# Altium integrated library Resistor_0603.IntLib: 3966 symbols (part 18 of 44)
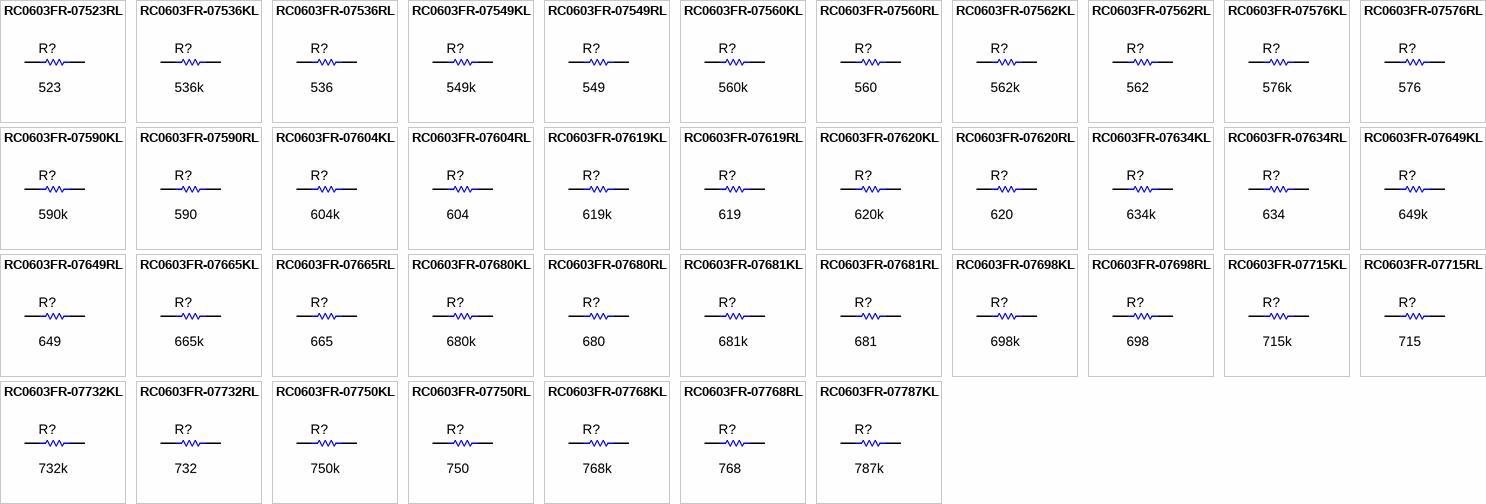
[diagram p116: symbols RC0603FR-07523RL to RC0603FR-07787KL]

## RC0603FR-07576RL
designator R?  ValueDisplayed: 576  (hidden comment: RC0603FR-07576RL)
RES, 576, 1%, 0.1 W, 0603; Manufacturer: Yageo America; CompType: Resistor; Value: 576; Value_Code: 576R; Tolerance_%: 1; Power_W: 0.1; Value2: 0.1W; VDC_V: 150; TempCo: 200 ppm/C; SizeArea_mm2: 1.28; SizeX_mm: 1.6; SizeY_mm: 0.8; EIA_Code: E96; U/M: EA; AEC Category: Q200; Green_Lifecycle: Active; Green_REACh: Passed
signal-integrity model Resistor
simulation model Resistor
footprint 0603
footprint 0603M
footprint 0603L
footprint 0603_HV
footprint 0603S
pins: 1, 2

## RC0603FR-07590KL
designator R?  ValueDisplayed: 590k  (hidden comment: RC0603FR-07590KL)
RES, 590 k, 1%, 0.1 W, 0603; Manufacturer: Yageo America; CompType: Resistor; Value: 590k; Res_ohm: 590000; Tolerance_%: 1; Power_W: 0.1; Value2: 0.1W; VDC_V: 150; TempCo: 200 ppm/C; SizeArea_mm2: 1.28; SizeX_mm: 1.6; SizeY_mm: 0.8; EIA_Code: E96; U/M: EA; AEC Category: Q200
signal-integrity model Resistor
simulation model Resistor
footprint 0603
footprint 0603M
footprint 0603L
footprint 0603_HV
footprint 0603S
pins: 1, 2

## RC0603FR-07590RL
designator R?  ValueDisplayed: 590  (hidden comment: RC0603FR-07590RL)
RES, 590, 1%, 0.1 W, 0603; Manufacturer: Yageo America; CompType: Resistor; Value: 590; Value_Code: 590R; Tolerance_%: 1; Power_W: 0.1; Value2: 0.1W; VDC_V: 150; TempCo: 200 ppm/C; SizeArea_mm2: 1.28; SizeX_mm: 1.6; SizeY_mm: 0.8; EIA_Code: E96; U/M: EA; AEC Category: Q200
signal-integrity model Resistor
simulation model Resistor
footprint 0603
footprint 0603M
footprint 0603L
footprint 0603_HV
footprint 0603S
pins: 1, 2

## RC0603FR-07604KL
designator R?  ValueDisplayed: 604k  (hidden comment: RC0603FR-07604KL)
RES, 604 k, 1%, 0.1 W, 0603; Manufacturer: Yageo America; CompType: Resistor; Value: 604k; Res_ohm: 604000; Tolerance_%: 1; Power_W: 0.1; Value2: 0.1W; VDC_V: 150; TempCo: 200 ppm/C; SizeArea_mm2: 1.28; SizeX_mm: 1.6; SizeY_mm: 0.8; EIA_Code: E96; U/M: EA; AEC Category: Q200; Green_Lifecycle: Active; Green_REACh: Passed
signal-integrity model Resistor
simulation model Resistor
footprint 0603
footprint 0603M
footprint 0603L
footprint 0603_HV
footprint 0603S
pins: 1, 2

## RC0603FR-07604RL
designator R?  ValueDisplayed: 604  (hidden comment: RC0603FR-07604RL)
RES, 604, 1%, 0.1 W, 0603; Manufacturer: Yageo America; CompType: Resistor; Value: 604; Value_Code: 604R; Tolerance_%: 1; Power_W: 0.1; Value2: 0.1W; VDC_V: 150; TempCo: 200 ppm/C; SizeArea_mm2: 1.28; SizeX_mm: 1.6; SizeY_mm: 0.8; EIA_Code: E96; U/M: EA; AEC Category: Q200; Green_Lifecycle: Active; Green_REACh: Passed
signal-integrity model Resistor
simulation model Resistor
footprint 0603
footprint 0603M
footprint 0603L
footprint 0603_HV
footprint 0603S
pins: 1, 2

## RC0603FR-07619KL
designator R?  ValueDisplayed: 619k  (hidden comment: RC0603FR-07619KL)
RES, 619 k, 1%, 0.1 W, 0603; Manufacturer: Yageo America; CompType: Resistor; Value: 619k; Res_ohm: 619000; Tolerance_%: 1; Power_W: 0.1; Value2: 0.1W; VDC_V: 150; TempCo: 200 ppm/C; SizeArea_mm2: 1.28; SizeX_mm: 1.6; SizeY_mm: 0.8; EIA_Code: E96; U/M: EA; AEC Category: Q200; Green_Lifecycle: Active; Green_REACh: Passed
signal-integrity model Resistor
simulation model Resistor
footprint 0603
footprint 0603M
footprint 0603L
footprint 0603_HV
footprint 0603S
pins: 1, 2

## RC0603FR-07619RL
designator R?  ValueDisplayed: 619  (hidden comment: RC0603FR-07619RL)
RES, 619, 1%, 0.1 W, 0603; Manufacturer: Yageo America; CompType: Resistor; Value: 619; Value_Code: 619R; Tolerance_%: 1; Power_W: 0.1; Value2: 0.1W; VDC_V: 150; TempCo: 200 ppm/C; SizeArea_mm2: 1.28; SizeX_mm: 1.6; SizeY_mm: 0.8; EIA_Code: E96; U/M: EA; AEC Category: Q200; Green_Lifecycle: Active; Green_REACh: Passed
signal-integrity model Resistor
simulation model Resistor
footprint 0603
footprint 0603M
footprint 0603L
footprint 0603_HV
footprint 0603S
pins: 1, 2

## RC0603FR-07620KL
designator R?  ValueDisplayed: 620k  (hidden comment: RC0603FR-07620KL)
RES, 620 k, 1%, 0.1 W, 0603; Manufacturer: Yageo America; CompType: Resistor; Value: 620k; Res_ohm: 620000; Tolerance_%: 1; Power_W: 0.1; Value2: 0.1W; VDC_V: 150; TempCo: 200 ppm/C; SizeArea_mm2: 1.28; SizeX_mm: 1.6; SizeY_mm: 0.8; U/M: EA; AEC Category: Q200; Green_Lifecycle: Active; Green_REACh: Passed
signal-integrity model Resistor
simulation model Resistor
footprint 0603
footprint 0603M
footprint 0603L
footprint 0603_HV
footprint 0603S
pins: 1, 2

## RC0603FR-07620RL
designator R?  ValueDisplayed: 620  (hidden comment: RC0603FR-07620RL)
RES, 620, 1%, 0.1 W, 0603; Manufacturer: Yageo America; CompType: Resistor; Value: 620; Value_Code: 620R; Tolerance_%: 1; Power_W: 0.1; Value2: 0.1W; VDC_V: 150; TempCo: 200 ppm/C; SizeArea_mm2: 1.28; SizeX_mm: 1.6; SizeY_mm: 0.8; U/M: EA; AEC Category: Q200
signal-integrity model Resistor
simulation model Resistor
footprint 0603
footprint 0603M
footprint 0603L
footprint 0603_HV
footprint 0603S
pins: 1, 2

## RC0603FR-07634KL
designator R?  ValueDisplayed: 634k  (hidden comment: RC0603FR-07634KL)
RES, 634 k, 1%, 0.1 W, 0603; Manufacturer: Yageo America; CompType: Resistor; Value: 634k; Res_ohm: 634000; Tolerance_%: 1; Power_W: 0.1; Value2: 0.1W; VDC_V: 150; TempCo: 200 ppm/C; SizeArea_mm2: 1.28; SizeX_mm: 1.6; SizeY_mm: 0.8; EIA_Code: E96; U/M: EA; AEC Category: Q200
signal-integrity model Resistor
simulation model Resistor
footprint 0603
footprint 0603M
footprint 0603L
footprint 0603_HV
footprint 0603S
pins: 1, 2

## RC0603FR-07634RL
designator R?  ValueDisplayed: 634  (hidden comment: RC0603FR-07634RL)
RES, 634, 1%, 0.1 W, 0603; Manufacturer: Yageo America; CompType: Resistor; Value: 634; Value_Code: 634R; Tolerance_%: 1; Power_W: 0.1; Value2: 0.1W; VDC_V: 150; TempCo: 200 ppm/C; SizeArea_mm2: 1.28; SizeX_mm: 1.6; SizeY_mm: 0.8; EIA_Code: E96; U/M: EA; AEC Category: Q200
signal-integrity model Resistor
simulation model Resistor
footprint 0603
footprint 0603M
footprint 0603L
footprint 0603_HV
footprint 0603S
pins: 1, 2

## RC0603FR-07649KL
designator R?  ValueDisplayed: 649k  (hidden comment: RC0603FR-07649KL)
RES, 649 k, 1%, 0.1 W, 0603; Manufacturer: Yageo America; CompType: Resistor; Value: 649k; Res_ohm: 649000; Tolerance_%: 1; Power_W: 0.1; Value2: 0.1W; VDC_V: 150; TempCo: 200 ppm/C; SizeArea_mm2: 1.28; SizeX_mm: 1.6; SizeY_mm: 0.8; EIA_Code: E96; U/M: EA; AEC Category: Q200
signal-integrity model Resistor
simulation model Resistor
footprint 0603
footprint 0603M
footprint 0603L
footprint 0603_HV
footprint 0603S
pins: 1, 2

## RC0603FR-07649RL
designator R?  ValueDisplayed: 649  (hidden comment: RC0603FR-07649RL)
RES, 649, 1%, 0.1 W, 0603; Manufacturer: Yageo America; CompType: Resistor; Value: 649; Value_Code: 649R; Tolerance_%: 1; Power_W: 0.1; Value2: 0.1W; VDC_V: 150; TempCo: 200 ppm/C; SizeArea_mm2: 1.28; SizeX_mm: 1.6; SizeY_mm: 0.8; EIA_Code: E96; U/M: EA; AEC Category: Q200; Green_Lifecycle: Active; Green_REACh: Passed
signal-integrity model Resistor
simulation model Resistor
footprint 0603
footprint 0603M
footprint 0603L
footprint 0603_HV
footprint 0603S
pins: 1, 2

## RC0603FR-07665KL
designator R?  ValueDisplayed: 665k  (hidden comment: RC0603FR-07665KL)
RES, 665 k, 1%, 0.1 W, 0603; Manufacturer: Yageo America; CompType: Resistor; Value: 665k; Res_ohm: 665000; Tolerance_%: 1; Power_W: 0.1; Value2: 0.1W; VDC_V: 150; TempCo: 200 ppm/C; SizeArea_mm2: 1.28; SizeX_mm: 1.6; SizeY_mm: 0.8; EIA_Code: E96; U/M: EA; AEC Category: Q200
signal-integrity model Resistor
simulation model Resistor
footprint 0603
footprint 0603M
footprint 0603L
footprint 0603_HV
footprint 0603S
pins: 1, 2

## RC0603FR-07665RL
designator R?  ValueDisplayed: 665  (hidden comment: RC0603FR-07665RL)
RES, 665, 1%, 0.1 W, 0603; Manufacturer: Yageo America; CompType: Resistor; Value: 665; Value_Code: 665R; Tolerance_%: 1; Power_W: 0.1; Value2: 0.1W; VDC_V: 150; TempCo: 200 ppm/C; SizeArea_mm2: 1.28; SizeX_mm: 1.6; SizeY_mm: 0.8; EIA_Code: E96; U/M: EA; AEC Category: Q200
signal-integrity model Resistor
simulation model Resistor
footprint 0603
footprint 0603M
footprint 0603L
footprint 0603_HV
footprint 0603S
pins: 1, 2

## RC0603FR-07680KL
designator R?  ValueDisplayed: 680k  (hidden comment: RC0603FR-07680KL)
RES, 680 k, 1%, 0.1 W, 0603; Manufacturer: Yageo America; CompType: Resistor; Value: 680k; Res_ohm: 680000; Tolerance_%: 1; Power_W: 0.1; Value2: 0.1W; VDC_V: 150; TempCo: 200 ppm/C; SizeArea_mm2: 1.28; SizeX_mm: 1.6; SizeY_mm: 0.8; U/M: EA; AEC Category: Q200; Green_Lifecycle: Active; Green_REACh: Passed
signal-integrity model Resistor
simulation model Resistor
footprint 0603
footprint 0603M
footprint 0603L
footprint 0603_HV
footprint 0603S
pins: 1, 2

## RC0603FR-07680RL
designator R?  ValueDisplayed: 680  (hidden comment: RC0603FR-07680RL)
RES, 680, 1%, 0.1 W, 0603; Manufacturer: Yageo America; CompType: Resistor; Value: 680; Value_Code: 680R; Tolerance_%: 1; Power_W: 0.1; Value2: 0.1W; VDC_V: 150; TempCo: 200 ppm/C; SizeArea_mm2: 1.28; SizeX_mm: 1.6; SizeY_mm: 0.8; U/M: EA; AEC Category: Q200; Green_Lifecycle: Active; Green_REACh: Passed
signal-integrity model Resistor
simulation model Resistor
footprint 0603
footprint 0603M
footprint 0603L
footprint 0603_HV
footprint 0603S
pins: 1, 2

## RC0603FR-07681KL
designator R?  ValueDisplayed: 681k  (hidden comment: RC0603FR-07681KL)
RES, 681 k, 1%, 0.1 W, 0603; Manufacturer: Yageo America; CompType: Resistor; Value: 681k; Res_ohm: 681000; Tolerance_%: 1; Power_W: 0.1; Value2: 0.1W; VDC_V: 150; TempCo: 200 ppm/C; SizeArea_mm2: 1.28; SizeX_mm: 1.6; SizeY_mm: 0.8; EIA_Code: E96; U/M: EA; AEC Category: Q200
signal-integrity model Resistor
simulation model Resistor
footprint 0603
footprint 0603M
footprint 0603L
footprint 0603_HV
footprint 0603S
pins: 1, 2

## RC0603FR-07681RL
designator R?  ValueDisplayed: 681  (hidden comment: RC0603FR-07681RL)
RES, 681, 1%, 0.1 W, 0603; Manufacturer: Yageo America; CompType: Resistor; Value: 681; Value_Code: 681R; Tolerance_%: 1; Power_W: 0.1; Value2: 0.1W; VDC_V: 150; TempCo: 200 ppm/C; SizeArea_mm2: 1.28; SizeX_mm: 1.6; SizeY_mm: 0.8; EIA_Code: E96; U/M: EA; AEC Category: Q200
signal-integrity model Resistor
simulation model Resistor
footprint 0603
footprint 0603M
footprint 0603L
footprint 0603_HV
footprint 0603S
pins: 1, 2

## RC0603FR-07698KL
designator R?  ValueDisplayed: 698k  (hidden comment: RC0603FR-07698KL)
RES, 698 k, 1%, 0.1 W, 0603; Manufacturer: Yageo America; CompType: Resistor; Value: 698k; Res_ohm: 698000; Tolerance_%: 1; Power_W: 0.1; Value2: 0.1W; VDC_V: 150; TempCo: 200 ppm/C; SizeArea_mm2: 1.28; SizeX_mm: 1.6; SizeY_mm: 0.8; EIA_Code: E96; U/M: EA; AEC Category: Q200
signal-integrity model Resistor
simulation model Resistor
footprint 0603
footprint 0603M
footprint 0603L
footprint 0603_HV
footprint 0603S
pins: 1, 2

## RC0603FR-07698RL
designator R?  ValueDisplayed: 698  (hidden comment: RC0603FR-07698RL)
RES, 698, 1%, 0.1 W, 0603; Manufacturer: Yageo America; CompType: Resistor; Value: 698; Value_Code: 698R; Tolerance_%: 1; Power_W: 0.1; Value2: 0.1W; VDC_V: 150; TempCo: 200 ppm/C; SizeArea_mm2: 1.28; SizeX_mm: 1.6; SizeY_mm: 0.8; EIA_Code: E96; U/M: EA; AEC Category: Q200
signal-integrity model Resistor
simulation model Resistor
footprint 0603
footprint 0603M
footprint 0603L
footprint 0603_HV
footprint 0603S
pins: 1, 2

## RC0603FR-07715KL
designator R?  ValueDisplayed: 715k  (hidden comment: RC0603FR-07715KL)
RES, 715 k, 1%, 0.1 W, 0603; Manufacturer: Yageo America; CompType: Resistor; Value: 715k; Res_ohm: 715000; Tolerance_%: 1; Power_W: 0.1; Value2: 0.1W; VDC_V: 150; TempCo: 200 ppm/C; SizeArea_mm2: 1.28; SizeX_mm: 1.6; SizeY_mm: 0.8; EIA_Code: E96; U/M: EA; AEC Category: Q200
signal-integrity model Resistor
simulation model Resistor
footprint 0603
footprint 0603M
footprint 0603L
footprint 0603_HV
footprint 0603S
pins: 1, 2

## RC0603FR-07715RL
designator R?  ValueDisplayed: 715  (hidden comment: RC0603FR-07715RL)
RES, 715, 1%, 0.1 W, 0603; Manufacturer: Yageo America; CompType: Resistor; Value: 715; Value_Code: 715R; Tolerance_%: 1; Power_W: 0.1; Value2: 0.1W; VDC_V: 150; TempCo: 200 ppm/C; SizeArea_mm2: 1.28; SizeX_mm: 1.6; SizeY_mm: 0.8; EIA_Code: E96; U/M: EA; AEC Category: Q200; Green_Lifecycle: Active; Green_REACh: Passed
signal-integrity model Resistor
simulation model Resistor
footprint 0603
footprint 0603M
footprint 0603L
footprint 0603_HV
footprint 0603S
pins: 1, 2

## RC0603FR-07732KL
designator R?  ValueDisplayed: 732k  (hidden comment: RC0603FR-07732KL)
RES, 732 k, 1%, 0.1 W, 0603; Manufacturer: Yageo America; CompType: Resistor; Value: 732k; Res_ohm: 732000; Tolerance_%: 1; Power_W: 0.1; Value2: 0.1W; VDC_V: 150; TempCo: 200 ppm/C; SizeArea_mm2: 1.28; SizeX_mm: 1.6; SizeY_mm: 0.8; EIA_Code: E96; U/M: EA; AEC Category: Q200
signal-integrity model Resistor
simulation model Resistor
footprint 0603
footprint 0603M
footprint 0603L
footprint 0603_HV
footprint 0603S
pins: 1, 2

## RC0603FR-07732RL
designator R?  ValueDisplayed: 732  (hidden comment: RC0603FR-07732RL)
RES, 732, 1%, 0.1 W, 0603; Manufacturer: Yageo America; CompType: Resistor; Value: 732; Value_Code: 732R; Tolerance_%: 1; Power_W: 0.1; Value2: 0.1W; VDC_V: 150; TempCo: 200 ppm/C; SizeArea_mm2: 1.28; SizeX_mm: 1.6; SizeY_mm: 0.8; EIA_Code: E96; U/M: EA; AEC Category: Q200; Green_Lifecycle: Active; Green_REACh: Passed
signal-integrity model Resistor
simulation model Resistor
footprint 0603
footprint 0603M
footprint 0603L
footprint 0603_HV
footprint 0603S
pins: 1, 2

## RC0603FR-07750KL
designator R?  ValueDisplayed: 750k  (hidden comment: RC0603FR-07750KL)
RES, 750 k, 1%, 0.1 W, 0603; Manufacturer: Yageo America; CompType: Resistor; Value: 750k; Res_ohm: 750000; Tolerance_%: 1; Power_W: 0.1; Value2: 0.1W; VDC_V: 150; TempCo: 200 ppm/C; SizeArea_mm2: 1.28; SizeX_mm: 1.6; SizeY_mm: 0.8; EIA_Code: E96; U/M: EA; AEC Category: Q200
signal-integrity model Resistor
simulation model Resistor
footprint 0603
footprint 0603M
footprint 0603L
footprint 0603_HV
footprint 0603S
pins: 1, 2

## RC0603FR-07750RL
designator R?  ValueDisplayed: 750  (hidden comment: RC0603FR-07750RL)
RES, 750, 1%, 0.1 W, 0603; Manufacturer: Yageo America; CompType: Resistor; Value: 750; Value_Code: 750R; Tolerance_%: 1; Power_W: 0.1; Value2: 0.1W; VDC_V: 150; TempCo: 200 ppm/C; SizeArea_mm2: 1.28; SizeX_mm: 1.6; SizeY_mm: 0.8; EIA_Code: E96; U/M: EA; AEC Category: Q200; Green_Lifecycle: Active; Green_REACh: Passed
signal-integrity model Resistor
simulation model Resistor
footprint 0603
footprint 0603M
footprint 0603L
footprint 0603_HV
footprint 0603S
pins: 1, 2

## RC0603FR-07768KL
designator R?  ValueDisplayed: 768k  (hidden comment: RC0603FR-07768KL)
RES, 768 k, 1%, 0.1 W, 0603; Manufacturer: Yageo America; CompType: Resistor; Value: 768k; Res_ohm: 768000; Tolerance_%: 1; Power_W: 0.1; Value2: 0.1W; VDC_V: 150; TempCo: 200 ppm/C; SizeArea_mm2: 1.28; SizeX_mm: 1.6; SizeY_mm: 0.8; EIA_Code: E96; U/M: EA; AEC Category: Q200; Green_Lifecycle: Active; Green_REACh: Passed
signal-integrity model Resistor
simulation model Resistor
footprint 0603
footprint 0603M
footprint 0603L
footprint 0603_HV
footprint 0603S
pins: 1, 2

## RC0603FR-07768RL
designator R?  ValueDisplayed: 768  (hidden comment: RC0603FR-07768RL)
RES, 768, 1%, 0.1 W, 0603; Manufacturer: Yageo America; CompType: Resistor; Value: 768; Value_Code: 768R; Tolerance_%: 1; Power_W: 0.1; Value2: 0.1W; VDC_V: 150; TempCo: 200 ppm/C; SizeArea_mm2: 1.28; SizeX_mm: 1.6; SizeY_mm: 0.8; EIA_Code: E96; U/M: EA; AEC Category: Q200; Green_Lifecycle: Active; Green_REACh: Passed
signal-integrity model Resistor
simulation model Resistor
footprint 0603
footprint 0603M
footprint 0603L
footprint 0603_HV
footprint 0603S
pins: 1, 2

## RC0603FR-07787KL
designator R?  ValueDisplayed: 787k  (hidden comment: RC0603FR-07787KL)
RES, 787 k, 1%, 0.1 W, 0603; Manufacturer: Yageo America; CompType: Resistor; Value: 787k; Res_ohm: 787000; Tolerance_%: 1; Power_W: 0.1; Value2: 0.1W; VDC_V: 150; TempCo: 200 ppm/C; SizeArea_mm2: 1.28; SizeX_mm: 1.6; SizeY_mm: 0.8; EIA_Code: E96; U/M: EA; AEC Category: Q200
signal-integrity model Resistor
simulation model Resistor
footprint 0603
footprint 0603M
footprint 0603L
footprint 0603_HV
footprint 0603S
pins: 1, 2

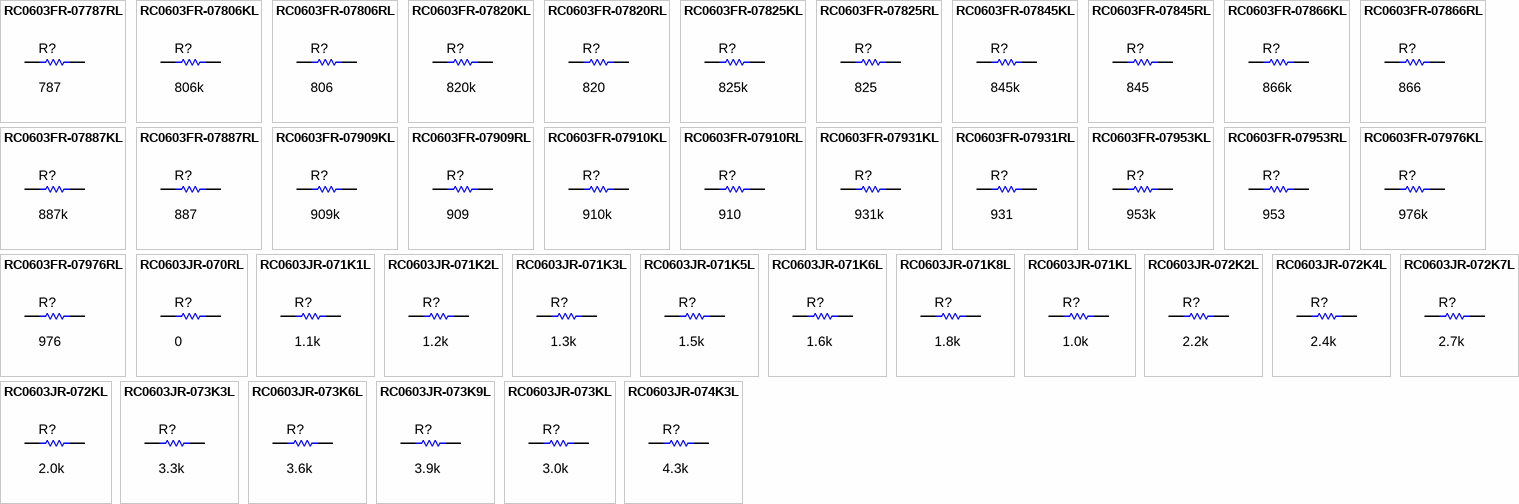
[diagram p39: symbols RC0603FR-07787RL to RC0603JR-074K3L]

## RC0603FR-07787RL
designator R?  ValueDisplayed: 787  (hidden comment: RC0603FR-07787RL)
RES, 787, 1%, 0.1 W, 0603; Manufacturer: Yageo America; CompType: Resistor; Value: 787; Value_Code: 787R; Tolerance_%: 1; Power_W: 0.1; Value2: 0.1W; VDC_V: 150; TempCo: 200 ppm/C; SizeArea_mm2: 1.28; SizeX_mm: 1.6; SizeY_mm: 0.8; EIA_Code: E96; U/M: EA; AEC Category: Q200; Green_Lifecycle: Active; Green_REACh: Passed
signal-integrity model Resistor
simulation model Resistor
footprint 0603
footprint 0603M
footprint 0603L
footprint 0603_HV
footprint 0603S
pins: 1, 2

## RC0603FR-07806KL
designator R?  ValueDisplayed: 806k  (hidden comment: RC0603FR-07806KL)
RES, 806 k, 1%, 0.1 W, 0603; Manufacturer: Yageo America; CompType: Resistor; Value: 806k; Res_ohm: 806000; Tolerance_%: 1; Power_W: 0.1; Value2: 0.1W; VDC_V: 150; TempCo: 200 ppm/C; SizeArea_mm2: 1.28; SizeX_mm: 1.6; SizeY_mm: 0.8; EIA_Code: E96; U/M: EA; AEC Category: Q200; Green_Lifecycle: Active; Green_REACh: Passed
signal-integrity model Resistor
simulation model Resistor
footprint 0603
footprint 0603M
footprint 0603L
footprint 0603_HV
footprint 0603S
pins: 1, 2

## RC0603FR-07806RL
designator R?  ValueDisplayed: 806  (hidden comment: RC0603FR-07806RL)
RES, 806, 1%, 0.1 W, 0603; Manufacturer: Yageo America; CompType: Resistor; Value: 806; Value_Code: 806R; Tolerance_%: 1; Power_W: 0.1; Value2: 0.1W; VDC_V: 150; TempCo: 200 ppm/C; SizeArea_mm2: 1.28; SizeX_mm: 1.6; SizeY_mm: 0.8; EIA_Code: E96; U/M: EA; AEC Category: Q200
signal-integrity model Resistor
simulation model Resistor
footprint 0603
footprint 0603M
footprint 0603L
footprint 0603_HV
footprint 0603S
pins: 1, 2

## RC0603FR-07820KL
designator R?  ValueDisplayed: 820k  (hidden comment: RC0603FR-07820KL)
RES, 820 k, 1%, 0.1 W, 0603; Manufacturer: Yageo America; CompType: Resistor; Value: 820k; Res_ohm: 820000; Tolerance_%: 1; Power_W: 0.1; Value2: 0.1W; VDC_V: 150; TempCo: 200 ppm/C; SizeArea_mm2: 1.28; SizeX_mm: 1.6; SizeY_mm: 0.8; U/M: EA; AEC Category: Q200
signal-integrity model Resistor
simulation model Resistor
footprint 0603
footprint 0603M
footprint 0603L
footprint 0603_HV
footprint 0603S
pins: 1, 2

## RC0603FR-07820RL
designator R?  ValueDisplayed: 820  (hidden comment: RC0603FR-07820RL)
RES, 820, 1%, 0.1 W, 0603; Manufacturer: Yageo America; CompType: Resistor; Value: 820; Value_Code: 820R; Tolerance_%: 1; Power_W: 0.1; Value2: 0.1W; VDC_V: 150; TempCo: 200 ppm/C; SizeArea_mm2: 1.28; SizeX_mm: 1.6; SizeY_mm: 0.8; U/M: EA; AEC Category: Q200
signal-integrity model Resistor
simulation model Resistor
footprint 0603
footprint 0603M
footprint 0603L
footprint 0603_HV
footprint 0603S
pins: 1, 2

## RC0603FR-07825KL
designator R?  ValueDisplayed: 825k  (hidden comment: RC0603FR-07825KL)
RES, 825 k, 1%, 0.1 W, 0603; Manufacturer: Yageo America; CompType: Resistor; Value: 825k; Res_ohm: 825000; Tolerance_%: 1; Power_W: 0.1; Value2: 0.1W; VDC_V: 150; TempCo: 200 ppm/C; SizeArea_mm2: 1.28; SizeX_mm: 1.6; SizeY_mm: 0.8; EIA_Code: E96; U/M: EA; AEC Category: Q200
signal-integrity model Resistor
simulation model Resistor
footprint 0603
footprint 0603M
footprint 0603L
footprint 0603_HV
footprint 0603S
pins: 1, 2

## RC0603FR-07825RL
designator R?  ValueDisplayed: 825  (hidden comment: RC0603FR-07825RL)
RES, 825, 1%, 0.1 W, 0603; Manufacturer: Yageo America; CompType: Resistor; Value: 825; Value_Code: 825R; Tolerance_%: 1; Power_W: 0.1; Value2: 0.1W; VDC_V: 150; TempCo: 200 ppm/C; SizeArea_mm2: 1.28; SizeX_mm: 1.6; SizeY_mm: 0.8; EIA_Code: E96; U/M: EA; AEC Category: Q200
signal-integrity model Resistor
simulation model Resistor
footprint 0603
footprint 0603M
footprint 0603L
footprint 0603_HV
footprint 0603S
pins: 1, 2

## RC0603FR-07845KL
designator R?  ValueDisplayed: 845k  (hidden comment: RC0603FR-07845KL)
RES, 845 k, 1%, 0.1 W, 0603; Manufacturer: Yageo America; CompType: Resistor; Value: 845k; Res_ohm: 845000; Tolerance_%: 1; Power_W: 0.1; Value2: 0.1W; VDC_V: 150; TempCo: 200 ppm/C; SizeArea_mm2: 1.28; SizeX_mm: 1.6; SizeY_mm: 0.8; EIA_Code: E96; U/M: EA; AEC Category: Q200; Green_Lifecycle: Active; Green_REACh: Passed
signal-integrity model Resistor
simulation model Resistor
footprint 0603
footprint 0603M
footprint 0603L
footprint 0603_HV
footprint 0603S
pins: 1, 2

## RC0603FR-07845RL
designator R?  ValueDisplayed: 845  (hidden comment: RC0603FR-07845RL)
RES, 845, 1%, 0.1 W, 0603; Manufacturer: Yageo America; CompType: Resistor; Value: 845; Value_Code: 845R; Tolerance_%: 1; Power_W: 0.1; Value2: 0.1W; VDC_V: 150; TempCo: 200 ppm/C; SizeArea_mm2: 1.28; SizeX_mm: 1.6; SizeY_mm: 0.8; EIA_Code: E96; U/M: EA; AEC Category: Q200; Green_Lifecycle: Active; Green_REACh: Passed
signal-integrity model Resistor
simulation model Resistor
footprint 0603
footprint 0603M
footprint 0603L
footprint 0603_HV
footprint 0603S
pins: 1, 2

## RC0603FR-07866KL
designator R?  ValueDisplayed: 866k  (hidden comment: RC0603FR-07866KL)
RES, 866 k, 1%, 0.1 W, 0603; Manufacturer: Yageo America; CompType: Resistor; Value: 866k; Res_ohm: 866000; Tolerance_%: 1; Power_W: 0.1; Value2: 0.1W; VDC_V: 150; TempCo: 200 ppm/C; SizeArea_mm2: 1.28; SizeX_mm: 1.6; SizeY_mm: 0.8; EIA_Code: E96; U/M: EA; AEC Category: Q200; Green_Lifecycle: Active; Green_REACh: Passed
signal-integrity model Resistor
simulation model Resistor
footprint 0603
footprint 0603M
footprint 0603L
footprint 0603_HV
footprint 0603S
pins: 1, 2

## RC0603FR-07866RL
designator R?  ValueDisplayed: 866  (hidden comment: RC0603FR-07866RL)
RES, 866, 1%, 0.1 W, 0603; Manufacturer: Yageo America; CompType: Resistor; Value: 866; Value_Code: 866R; Tolerance_%: 1; Power_W: 0.1; Value2: 0.1W; VDC_V: 150; TempCo: 200 ppm/C; SizeArea_mm2: 1.28; SizeX_mm: 1.6; SizeY_mm: 0.8; EIA_Code: E96; U/M: EA; AEC Category: Q200
signal-integrity model Resistor
simulation model Resistor
footprint 0603
footprint 0603M
footprint 0603L
footprint 0603_HV
footprint 0603S
pins: 1, 2

## RC0603FR-07887KL
designator R?  ValueDisplayed: 887k  (hidden comment: RC0603FR-07887KL)
RES, 887 k, 1%, 0.1 W, 0603; Manufacturer: Yageo America; CompType: Resistor; Value: 887k; Res_ohm: 887000; Tolerance_%: 1; Power_W: 0.1; Value2: 0.1W; VDC_V: 150; TempCo: 200 ppm/C; SizeArea_mm2: 1.28; SizeX_mm: 1.6; SizeY_mm: 0.8; EIA_Code: E96; U/M: EA; AEC Category: Q200
signal-integrity model Resistor
simulation model Resistor
footprint 0603
footprint 0603M
footprint 0603L
footprint 0603_HV
footprint 0603S
pins: 1, 2

## RC0603FR-07887RL
designator R?  ValueDisplayed: 887  (hidden comment: RC0603FR-07887RL)
RES, 887, 1%, 0.1 W, 0603; Manufacturer: Yageo America; CompType: Resistor; Value: 887; Value_Code: 887R; Tolerance_%: 1; Power_W: 0.1; Value2: 0.1W; VDC_V: 150; TempCo: 200 ppm/C; SizeArea_mm2: 1.28; SizeX_mm: 1.6; SizeY_mm: 0.8; EIA_Code: E96; U/M: EA; AEC Category: Q200
signal-integrity model Resistor
simulation model Resistor
footprint 0603
footprint 0603M
footprint 0603L
footprint 0603_HV
footprint 0603S
pins: 1, 2

## RC0603FR-07909KL
designator R?  ValueDisplayed: 909k  (hidden comment: RC0603FR-07909KL)
RES, 909 k, 1%, 0.1 W, 0603; Manufacturer: Yageo America; CompType: Resistor; Value: 909k; Res_ohm: 909000; Tolerance_%: 1; Power_W: 0.1; Value2: 0.1W; VDC_V: 150; TempCo: 200 ppm/C; SizeArea_mm2: 1.28; SizeX_mm: 1.6; SizeY_mm: 0.8; EIA_Code: E96; U/M: EA; AEC Category: Q200
signal-integrity model Resistor
simulation model Resistor
footprint 0603
footprint 0603M
footprint 0603L
footprint 0603_HV
footprint 0603S
pins: 1, 2

## RC0603FR-07909RL
designator R?  ValueDisplayed: 909  (hidden comment: RC0603FR-07909RL)
RES, 909, 1%, 0.1 W, 0603; Manufacturer: Yageo America; CompType: Resistor; Value: 909; Value_Code: 909R; Tolerance_%: 1; Power_W: 0.1; Value2: 0.1W; VDC_V: 150; TempCo: 200 ppm/C; SizeArea_mm2: 1.28; SizeX_mm: 1.6; SizeY_mm: 0.8; EIA_Code: E96; U/M: EA; AEC Category: Q200
signal-integrity model Resistor
simulation model Resistor
footprint 0603
footprint 0603M
footprint 0603L
footprint 0603_HV
footprint 0603S
pins: 1, 2

## RC0603FR-07910KL
designator R?  ValueDisplayed: 910k  (hidden comment: RC0603FR-07910KL)
RES, 910 k, 1%, 0.1 W, 0603; Manufacturer: Yageo America; CompType: Resistor; Value: 910k; Res_ohm: 910000; Tolerance_%: 1; Power_W: 0.1; Value2: 0.1W; VDC_V: 150; TempCo: 200 ppm/C; SizeArea_mm2: 1.28; SizeX_mm: 1.6; SizeY_mm: 0.8; U/M: EA; AEC Category: Q200
signal-integrity model Resistor
simulation model Resistor
footprint 0603
footprint 0603M
footprint 0603L
footprint 0603_HV
footprint 0603S
pins: 1, 2

## RC0603FR-07910RL
designator R?  ValueDisplayed: 910  (hidden comment: RC0603FR-07910RL)
RES, 910, 1%, 0.1 W, 0603; Manufacturer: Yageo America; CompType: Resistor; Value: 910; Value_Code: 910R; Tolerance_%: 1; Power_W: 0.1; Value2: 0.1W; VDC_V: 150; TempCo: 200 ppm/C; SizeArea_mm2: 1.28; SizeX_mm: 1.6; SizeY_mm: 0.8; U/M: EA; AEC Category: Q200
signal-integrity model Resistor
simulation model Resistor
footprint 0603
footprint 0603M
footprint 0603L
footprint 0603_HV
footprint 0603S
pins: 1, 2

## RC0603FR-07931KL
designator R?  ValueDisplayed: 931k  (hidden comment: RC0603FR-07931KL)
RES, 931 k, 1%, 0.1 W, 0603; Manufacturer: Yageo America; CompType: Resistor; Value: 931k; Res_ohm: 931000; Tolerance_%: 1; Power_W: 0.1; Value2: 0.1W; VDC_V: 150; TempCo: 200 ppm/C; SizeArea_mm2: 1.28; SizeX_mm: 1.6; SizeY_mm: 0.8; EIA_Code: E96; U/M: EA; AEC Category: Q200
signal-integrity model Resistor
simulation model Resistor
footprint 0603
footprint 0603M
footprint 0603L
footprint 0603_HV
footprint 0603S
pins: 1, 2

## RC0603FR-07931RL
designator R?  ValueDisplayed: 931  (hidden comment: RC0603FR-07931RL)
RES, 931, 1%, 0.1 W, 0603; Manufacturer: Yageo America; CompType: Resistor; Value: 931; Value_Code: 931R; Tolerance_%: 1; Power_W: 0.1; Value2: 0.1W; VDC_V: 150; TempCo: 200 ppm/C; SizeArea_mm2: 1.28; SizeX_mm: 1.6; SizeY_mm: 0.8; EIA_Code: E96; U/M: EA; AEC Category: Q200
signal-integrity model Resistor
simulation model Resistor
footprint 0603
footprint 0603M
footprint 0603L
footprint 0603_HV
footprint 0603S
pins: 1, 2

## RC0603FR-07953KL
designator R?  ValueDisplayed: 953k  (hidden comment: RC0603FR-07953KL)
RES, 953 k, 1%, 0.1 W, 0603; Manufacturer: Yageo America; CompType: Resistor; Value: 953k; Res_ohm: 953000; Tolerance_%: 1; Power_W: 0.1; Value2: 0.1W; VDC_V: 150; TempCo: 200 ppm/C; SizeArea_mm2: 1.28; SizeX_mm: 1.6; SizeY_mm: 0.8; EIA_Code: E96; U/M: EA; AEC Category: Q200
signal-integrity model Resistor
simulation model Resistor
footprint 0603
footprint 0603M
footprint 0603L
footprint 0603_HV
footprint 0603S
pins: 1, 2

## RC0603FR-07953RL
designator R?  ValueDisplayed: 953  (hidden comment: RC0603FR-07953RL)
RES, 953, 1%, 0.1 W, 0603; Manufacturer: Yageo America; CompType: Resistor; Value: 953; Value_Code: 953R; Tolerance_%: 1; Power_W: 0.1; Value2: 0.1W; VDC_V: 150; TempCo: 200 ppm/C; SizeArea_mm2: 1.28; SizeX_mm: 1.6; SizeY_mm: 0.8; EIA_Code: E96; U/M: EA; AEC Category: Q200; Green_Lifecycle: Active; Green_REACh: Passed
signal-integrity model Resistor
simulation model Resistor
footprint 0603
footprint 0603M
footprint 0603L
footprint 0603_HV
footprint 0603S
pins: 1, 2

## RC0603FR-07976KL
designator R?  ValueDisplayed: 976k  (hidden comment: RC0603FR-07976KL)
RES, 976 k, 1%, 0.1 W, 0603; Manufacturer: Yageo America; CompType: Resistor; Value: 976k; Res_ohm: 976000; Tolerance_%: 1; Power_W: 0.1; Value2: 0.1W; VDC_V: 150; TempCo: 200 ppm/C; SizeArea_mm2: 1.28; SizeX_mm: 1.6; SizeY_mm: 0.8; EIA_Code: E96; U/M: EA; AEC Category: Q200
signal-integrity model Resistor
simulation model Resistor
footprint 0603
footprint 0603M
footprint 0603L
footprint 0603_HV
footprint 0603S
pins: 1, 2

## RC0603FR-07976RL
designator R?  ValueDisplayed: 976  (hidden comment: RC0603FR-07976RL)
RES, 976, 1%, 0.1 W, 0603; Manufacturer: Yageo America; CompType: Resistor; Value: 976; Value_Code: 976R; Tolerance_%: 1; Power_W: 0.1; Value2: 0.1W; VDC_V: 150; TempCo: 200 ppm/C; SizeArea_mm2: 1.28; SizeX_mm: 1.6; SizeY_mm: 0.8; EIA_Code: E96; U/M: EA; AEC Category: Q200
signal-integrity model Resistor
simulation model Resistor
footprint 0603
footprint 0603M
footprint 0603L
footprint 0603_HV
footprint 0603S
pins: 1, 2

## RC0603JR-070RL
designator R?  ValueDisplayed: 0  (hidden comment: RC0603JR-070RL)
RES, 0, 5%, 0.1 W, 0603; Manufacturer: Yageo America; CompType: Resistor; Value: 0; Value_Code: 0000; Tolerance_%: 5; Power_W: 0.1; Value2: 0.1W; VDC_V: 50; TempCo: 200 ppm/C; SizeArea_mm2: 1.28; SizeX_mm: 1.6; SizeY_mm: 0.8; SizeZ_mm: 1; EIA_Code: E24; U/M: EA; AEC Category: Q200; Green_Lifecycle: Active; Green_REACh: Passed
signal-integrity model Resistor
simulation model Resistor
footprint 0603
footprint 0603M
footprint 0603L
footprint 0603_HV
footprint 0603S
pins: 1, 2

## RC0603JR-071K1L
designator R?  ValueDisplayed: 1.1k  (hidden comment: RC0603JR-071K1L)
RES, 1.1 k, 5%, 0.1 W, 0603; Manufacturer: Yageo America; CompType: Resistor; Value: 1.1k; Res_ohm: 1100; Value_Code: 1k10; Tolerance_%: 5; Power_W: 0.1; Value2: 0.1W; VDC_V: 50; TempCo: 100 ppm/C; SizeArea_mm2: 1.28; SizeX_mm: 1.6; SizeY_mm: 0.8; SizeZ_mm: 1; EIA_Code: E24; U/M: EA; AEC Category: Q200
signal-integrity model Resistor
simulation model Resistor
footprint 0603
footprint 0603M
footprint 0603L
footprint 0603_HV
footprint 0603S
pins: 1, 2

## RC0603JR-071K2L
designator R?  ValueDisplayed: 1.2k  (hidden comment: RC0603JR-071K2L)
RES, 1.2 k, 5%, 0.1 W, 0603; Manufacturer: Yageo America; CompType: Resistor; Value: 1.2k; Res_ohm: 1200; Value_Code: 1k20; Tolerance_%: 5; Power_W: 0.1; Value2: 0.1W; VDC_V: 50; TempCo: 100 ppm/C; SizeArea_mm2: 1.28; SizeX_mm: 1.6; SizeY_mm: 0.8; SizeZ_mm: 1; EIA_Code: E24; U/M: EA; AEC Category: Q200; Green_Lifecycle: Active; Green_REACh: Passed
signal-integrity model Resistor
simulation model Resistor
footprint 0603
footprint 0603M
footprint 0603L
footprint 0603_HV
footprint 0603S
pins: 1, 2

## RC0603JR-071K3L
designator R?  ValueDisplayed: 1.3k  (hidden comment: RC0603JR-071K3L)
RES, 1.3 k, 5%, 0.1 W, 0603; Manufacturer: Yageo America; CompType: Resistor; Value: 1.3k; Res_ohm: 1300; Value_Code: 1k30; Tolerance_%: 5; Power_W: 0.1; Value2: 0.1W; VDC_V: 50; TempCo: 100 ppm/C; SizeArea_mm2: 1.28; SizeX_mm: 1.6; SizeY_mm: 0.8; SizeZ_mm: 1; EIA_Code: E24; U/M: EA; AEC Category: Q200; Green_Lifecycle: Active; Green_REACh: Passed
signal-integrity model Resistor
simulation model Resistor
footprint 0603
footprint 0603M
footprint 0603L
footprint 0603_HV
footprint 0603S
pins: 1, 2

## RC0603JR-071K5L
designator R?  ValueDisplayed: 1.5k  (hidden comment: RC0603JR-071K5L)
RES, 1.5 k, 5%, 0.1 W, 0603; Manufacturer: Yageo America; CompType: Resistor; Value: 1.5k; Res_ohm: 1500; Value_Code: 1k50; Tolerance_%: 5; Power_W: 0.1; Value2: 0.1W; VDC_V: 50; TempCo: 100 ppm/C; SizeArea_mm2: 1.28; SizeX_mm: 1.6; SizeY_mm: 0.8; SizeZ_mm: 1; EIA_Code: E24; U/M: EA; AEC Category: Q200; Green_Lifecycle: Active; Green_REACh: Passed
signal-integrity model Resistor
simulation model Resistor
footprint 0603
footprint 0603M
footprint 0603L
footprint 0603_HV
footprint 0603S
pins: 1, 2

## RC0603JR-071K6L
designator R?  ValueDisplayed: 1.6k  (hidden comment: RC0603JR-071K6L)
RES, 1.6 k, 5%, 0.1 W, 0603; Manufacturer: Yageo America; CompType: Resistor; Value: 1.6k; Res_ohm: 1600; Value_Code: 1k60; Tolerance_%: 5; Power_W: 0.1; Value2: 0.1W; VDC_V: 50; TempCo: 100 ppm/C; SizeArea_mm2: 1.28; SizeX_mm: 1.6; SizeY_mm: 0.8; SizeZ_mm: 1; EIA_Code: E24; U/M: EA; AEC Category: Q200
signal-integrity model Resistor
simulation model Resistor
footprint 0603
footprint 0603M
footprint 0603L
footprint 0603_HV
footprint 0603S
pins: 1, 2

## RC0603JR-071K8L
designator R?  ValueDisplayed: 1.8k  (hidden comment: RC0603JR-071K8L)
RES, 1.8 k, 5%, 0.1 W, 0603; Manufacturer: Yageo America; CompType: Resistor; Value: 1.8k; Res_ohm: 1800; Value_Code: 1k80; Tolerance_%: 5; Power_W: 0.1; Value2: 0.1W; VDC_V: 50; TempCo: 100 ppm/C; SizeArea_mm2: 1.28; SizeX_mm: 1.6; SizeY_mm: 0.8; SizeZ_mm: 1; EIA_Code: E24; U/M: EA; AEC Category: Q200
signal-integrity model Resistor
simulation model Resistor
footprint 0603
footprint 0603M
footprint 0603L
footprint 0603_HV
footprint 0603S
pins: 1, 2

## RC0603JR-071KL
designator R?  ValueDisplayed: 1.0k  (hidden comment: RC0603JR-071KL)
RES, 1.0 k, 5%, 0.1 W, 0603; Manufacturer: Yageo America; CompType: Resistor; Value: 1.0k; Res_ohm: 1000; Value_Code: 1k00; Tolerance_%: 5; Power_W: 0.1; Value2: 0.1W; VDC_V: 50; TempCo: 100 ppm/C; SizeArea_mm2: 1.28; SizeX_mm: 1.6; SizeY_mm: 0.8; SizeZ_mm: 1; EIA_Code: E24; U/M: EA; AEC Category: Q200; Green_Lifecycle: Active; Green_REACh: Passed
signal-integrity model Resistor
simulation model Resistor
footprint 0603
footprint 0603M
footprint 0603L
footprint 0603_HV
footprint 0603S
pins: 1, 2

## RC0603JR-072K2L
designator R?  ValueDisplayed: 2.2k  (hidden comment: RC0603JR-072K2L)
RES, 2.2 k, 5%, 0.1 W, 0603; Manufacturer: Yageo America; CompType: Resistor; Value: 2.2k; Res_ohm: 2200; Value_Code: 2k20; Tolerance_%: 5; Power_W: 0.1; Value2: 0.1W; VDC_V: 50; TempCo: 100 ppm/C; SizeArea_mm2: 1.28; SizeX_mm: 1.6; SizeY_mm: 0.8; SizeZ_mm: 1; EIA_Code: E24; U/M: EA; AEC Category: Q200; Green_Lifecycle: Active; Green_REACh: Passed
signal-integrity model Resistor
simulation model Resistor
footprint 0603
footprint 0603M
footprint 0603L
footprint 0603_HV
footprint 0603S
pins: 1, 2

## RC0603JR-072K4L
designator R?  ValueDisplayed: 2.4k  (hidden comment: RC0603JR-072K4L)
RES, 2.4 k, 5%, 0.1 W, 0603; Manufacturer: Yageo America; CompType: Resistor; Value: 2.4k; Res_ohm: 2400; Value_Code: 2k40; Tolerance_%: 5; Power_W: 0.1; Value2: 0.1W; VDC_V: 50; TempCo: 100 ppm/C; SizeArea_mm2: 1.28; SizeX_mm: 1.6; SizeY_mm: 0.8; SizeZ_mm: 1; EIA_Code: E24; U/M: EA; AEC Category: Q200
signal-integrity model Resistor
simulation model Resistor
footprint 0603
footprint 0603M
footprint 0603L
footprint 0603_HV
footprint 0603S
pins: 1, 2

## RC0603JR-072K7L
designator R?  ValueDisplayed: 2.7k  (hidden comment: RC0603JR-072K7L)
RES, 2.7 k, 5%, 0.1 W, 0603; Manufacturer: Yageo America; CompType: Resistor; Value: 2.7k; Res_ohm: 2700; Value_Code: 2k70; Tolerance_%: 5; Power_W: 0.1; Value2: 0.1W; VDC_V: 50; TempCo: 100 ppm/C; SizeArea_mm2: 1.28; SizeX_mm: 1.6; SizeY_mm: 0.8; SizeZ_mm: 1; EIA_Code: E24; U/M: EA; AEC Category: Q200; Green_Lifecycle: Active; Green_REACh: Passed
signal-integrity model Resistor
simulation model Resistor
footprint 0603
footprint 0603M
footprint 0603L
footprint 0603_HV
footprint 0603S
pins: 1, 2

## RC0603JR-072KL
designator R?  ValueDisplayed: 2.0k  (hidden comment: RC0603JR-072KL)
RES, 2.0 k, 5%, 0.1 W, 0603; Manufacturer: Yageo America; CompType: Resistor; Value: 2.0k; Res_ohm: 2000; Value_Code: 2k00; Tolerance_%: 5; Power_W: 0.1; Value2: 0.1W; VDC_V: 50; TempCo: 100 ppm/C; SizeArea_mm2: 1.28; SizeX_mm: 1.6; SizeY_mm: 0.8; SizeZ_mm: 1; EIA_Code: E24; U/M: EA; AEC Category: Q200; Green_Lifecycle: Active; Green_REACh: Passed
signal-integrity model Resistor
simulation model Resistor
footprint 0603
footprint 0603M
footprint 0603L
footprint 0603_HV
footprint 0603S
pins: 1, 2

## RC0603JR-073K3L
designator R?  ValueDisplayed: 3.3k  (hidden comment: RC0603JR-073K3L)
RES, 3.3 k, 5%, 0.1 W, 0603; Manufacturer: Yageo America; CompType: Resistor; Value: 3.3k; Res_ohm: 3300; Value_Code: 3k30; Tolerance_%: 5; Power_W: 0.1; Value2: 0.1W; VDC_V: 50; TempCo: 100 ppm/C; SizeArea_mm2: 1.28; SizeX_mm: 1.6; SizeY_mm: 0.8; SizeZ_mm: 1; EIA_Code: E24; U/M: EA; AEC Category: Q200; Green_Lifecycle: Active; Green_REACh: Passed
signal-integrity model Resistor
simulation model Resistor
footprint 0603
footprint 0603M
footprint 0603L
footprint 0603_HV
footprint 0603S
pins: 1, 2

## RC0603JR-073K6L
designator R?  ValueDisplayed: 3.6k  (hidden comment: RC0603JR-073K6L)
RES, 3.6 k, 5%, 0.1 W, 0603; Manufacturer: Yageo America; CompType: Resistor; Value: 3.6k; Res_ohm: 3600; Value_Code: 3k60; Tolerance_%: 5; Power_W: 0.1; Value2: 0.1W; VDC_V: 50; TempCo: 100 ppm/C; SizeArea_mm2: 1.28; SizeX_mm: 1.6; SizeY_mm: 0.8; SizeZ_mm: 1; EIA_Code: E24; U/M: EA; AEC Category: Q200
signal-integrity model Resistor
simulation model Resistor
footprint 0603
footprint 0603M
footprint 0603L
footprint 0603_HV
footprint 0603S
pins: 1, 2

## RC0603JR-073K9L
designator R?  ValueDisplayed: 3.9k  (hidden comment: RC0603JR-073K9L)
RES, 3.9 k, 5%, 0.1 W, 0603; Manufacturer: Yageo America; CompType: Resistor; Value: 3.9k; Res_ohm: 3900; Value_Code: 3k90; Tolerance_%: 5; Power_W: 0.1; Value2: 0.1W; VDC_V: 50; TempCo: 100 ppm/C; SizeArea_mm2: 1.28; SizeX_mm: 1.6; SizeY_mm: 0.8; SizeZ_mm: 1; EIA_Code: E24; U/M: EA; AEC Category: Q200
signal-integrity model Resistor
simulation model Resistor
footprint 0603
footprint 0603M
footprint 0603L
footprint 0603_HV
footprint 0603S
pins: 1, 2

## RC0603JR-073KL
designator R?  ValueDisplayed: 3.0k  (hidden comment: RC0603JR-073KL)
RES, 3.0 k, 5%, 0.1 W, 0603; Manufacturer: Yageo America; CompType: Resistor; Value: 3.0k; Res_ohm: 3000; Value_Code: 3k00; Tolerance_%: 5; Power_W: 0.1; Value2: 0.1W; VDC_V: 50; TempCo: 100 ppm/C; SizeArea_mm2: 1.28; SizeX_mm: 1.6; SizeY_mm: 0.8; SizeZ_mm: 1; EIA_Code: E24; U/M: EA; AEC Category: Q200
signal-integrity model Resistor
simulation model Resistor
footprint 0603
footprint 0603M
footprint 0603L
footprint 0603_HV
footprint 0603S
pins: 1, 2

## RC0603JR-074K3L
designator R?  ValueDisplayed: 4.3k  (hidden comment: RC0603JR-074K3L)
RES, 4.3 k, 5%, 0.1 W, 0603; Manufacturer: Yageo America; CompType: Resistor; Value: 4.3k; Res_ohm: 4300; Value_Code: 4k30; Tolerance_%: 5; Power_W: 0.1; Value2: 0.1W; VDC_V: 50; TempCo: 100 ppm/C; SizeArea_mm2: 1.28; SizeX_mm: 1.6; SizeY_mm: 0.8; SizeZ_mm: 1; EIA_Code: E24; U/M: EA; AEC Category: Q200
signal-integrity model Resistor
simulation model Resistor
footprint 0603
footprint 0603M
footprint 0603L
footprint 0603_HV
footprint 0603S
pins: 1, 2

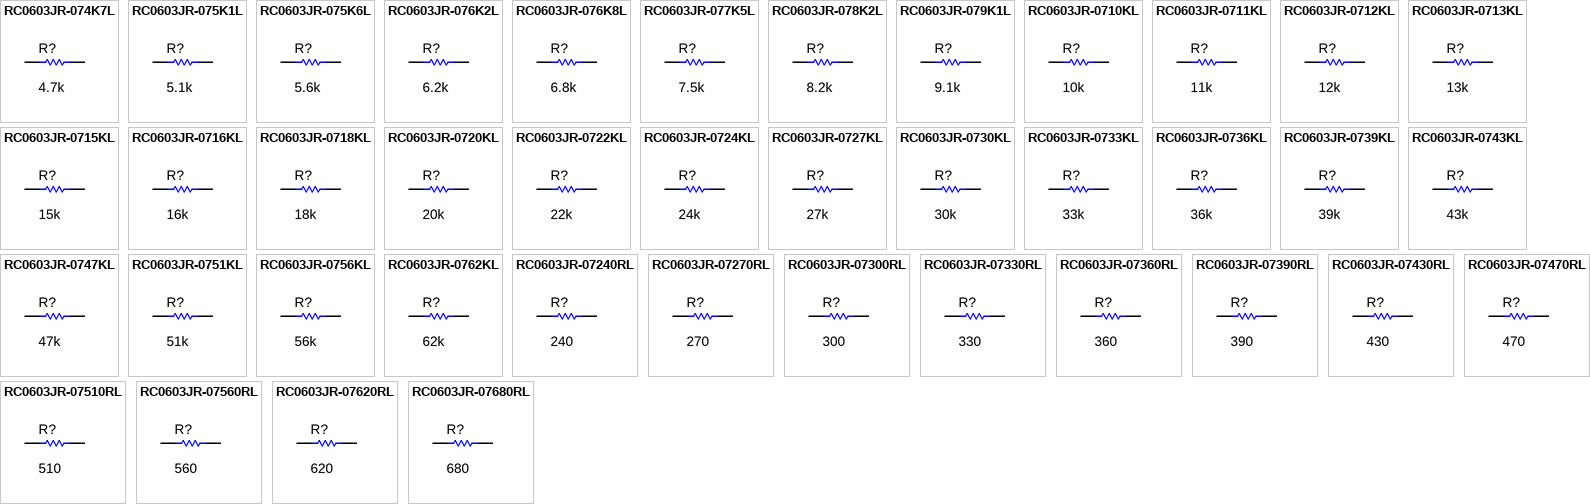
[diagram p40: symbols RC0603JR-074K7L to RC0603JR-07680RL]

## RC0603JR-074K7L
designator R?  ValueDisplayed: 4.7k  (hidden comment: RC0603JR-074K7L)
RES, 4.7 k, 5%, 0.1 W, 0603; Manufacturer: Yageo America; CompType: Resistor; Value: 4.7k; Res_ohm: 4700; Value_Code: 4k70; Tolerance_%: 5; Power_W: 0.1; Value2: 0.1W; VDC_V: 50; TempCo: 100 ppm/C; SizeArea_mm2: 1.28; SizeX_mm: 1.6; SizeY_mm: 0.8; SizeZ_mm: 1; EIA_Code: E24; U/M: EA; AEC Category: Q200; Green_Lifecycle: Active; Green_REACh: Passed
signal-integrity model Resistor
simulation model Resistor
footprint 0603
footprint 0603M
footprint 0603L
footprint 0603_HV
footprint 0603S
pins: 1, 2

## RC0603JR-075K1L
designator R?  ValueDisplayed: 5.1k  (hidden comment: RC0603JR-075K1L)
RES, 5.1 k, 5%, 0.1 W, 0603; Manufacturer: Yageo America; CompType: Resistor; Value: 5.1k; Res_ohm: 5100; Value_Code: 5k10; Tolerance_%: 5; Power_W: 0.1; Value2: 0.1W; VDC_V: 50; TempCo: 100 ppm/C; SizeArea_mm2: 1.28; SizeX_mm: 1.6; SizeY_mm: 0.8; SizeZ_mm: 1; EIA_Code: E24; U/M: EA; AEC Category: Q200
signal-integrity model Resistor
simulation model Resistor
footprint 0603
footprint 0603M
footprint 0603L
footprint 0603_HV
footprint 0603S
pins: 1, 2

## RC0603JR-075K6L
designator R?  ValueDisplayed: 5.6k  (hidden comment: RC0603JR-075K6L)
RES, 5.6 k, 5%, 0.1 W, 0603; Manufacturer: Yageo America; CompType: Resistor; Value: 5.6k; Res_ohm: 5600; Value_Code: 5k60; Tolerance_%: 5; Power_W: 0.1; Value2: 0.1W; VDC_V: 50; TempCo: 100 ppm/C; SizeArea_mm2: 1.28; SizeX_mm: 1.6; SizeY_mm: 0.8; SizeZ_mm: 1; EIA_Code: E24; U/M: EA; AEC Category: Q200; Green_Lifecycle: Active; Green_REACh: Passed
signal-integrity model Resistor
simulation model Resistor
footprint 0603
footprint 0603M
footprint 0603L
footprint 0603_HV
footprint 0603S
pins: 1, 2

## RC0603JR-076K2L
designator R?  ValueDisplayed: 6.2k  (hidden comment: RC0603JR-076K2L)
RES, 6.2 k, 5%, 0.1 W, 0603; Manufacturer: Yageo America; CompType: Resistor; Value: 6.2k; Res_ohm: 6200; Value_Code: 6k20; Tolerance_%: 5; Power_W: 0.1; Value2: 0.1W; VDC_V: 50; TempCo: 100 ppm/C; SizeArea_mm2: 1.28; SizeX_mm: 1.6; SizeY_mm: 0.8; SizeZ_mm: 1; EIA_Code: E24; U/M: EA; AEC Category: Q200
signal-integrity model Resistor
simulation model Resistor
footprint 0603
footprint 0603M
footprint 0603L
footprint 0603_HV
footprint 0603S
pins: 1, 2

## RC0603JR-076K8L
designator R?  ValueDisplayed: 6.8k  (hidden comment: RC0603JR-076K8L)
RES, 6.8 k, 5%, 0.1 W, 0603; Manufacturer: Yageo America; CompType: Resistor; Value: 6.8k; Res_ohm: 6800; Value_Code: 6k80; Tolerance_%: 5; Power_W: 0.1; Value2: 0.1W; VDC_V: 50; TempCo: 100 ppm/C; SizeArea_mm2: 1.28; SizeX_mm: 1.6; SizeY_mm: 0.8; SizeZ_mm: 1; EIA_Code: E24; U/M: EA; AEC Category: Q200
signal-integrity model Resistor
simulation model Resistor
footprint 0603
footprint 0603M
footprint 0603L
footprint 0603_HV
footprint 0603S
pins: 1, 2

## RC0603JR-077K5L
designator R?  ValueDisplayed: 7.5k  (hidden comment: RC0603JR-077K5L)
RES, 7.5 k, 5%, 0.1 W, 0603; Manufacturer: Yageo America; CompType: Resistor; Value: 7.5k; Res_ohm: 7500; Value_Code: 7k50; Tolerance_%: 5; Power_W: 0.1; Value2: 0.1W; VDC_V: 50; TempCo: 100 ppm/C; SizeArea_mm2: 1.28; SizeX_mm: 1.6; SizeY_mm: 0.8; SizeZ_mm: 1; EIA_Code: E24; U/M: EA; AEC Category: Q200
signal-integrity model Resistor
simulation model Resistor
footprint 0603
footprint 0603M
footprint 0603L
footprint 0603_HV
footprint 0603S
pins: 1, 2

## RC0603JR-078K2L
designator R?  ValueDisplayed: 8.2k  (hidden comment: RC0603JR-078K2L)
RES, 8.2 k, 5%, 0.1 W, 0603; Manufacturer: Yageo America; CompType: Resistor; Value: 8.2k; Res_ohm: 8200; Value_Code: 8k20; Tolerance_%: 5; Power_W: 0.1; Value2: 0.1W; VDC_V: 50; TempCo: 100 ppm/C; SizeArea_mm2: 1.28; SizeX_mm: 1.6; SizeY_mm: 0.8; SizeZ_mm: 1; EIA_Code: E24; U/M: EA; AEC Category: Q200; Green_Lifecycle: Active; Green_REACh: Passed
signal-integrity model Resistor
simulation model Resistor
footprint 0603
footprint 0603M
footprint 0603L
footprint 0603_HV
footprint 0603S
pins: 1, 2

## RC0603JR-079K1L
designator R?  ValueDisplayed: 9.1k  (hidden comment: RC0603JR-079K1L)
RES, 9.1 k, 5%, 0.1 W, 0603; Manufacturer: Yageo America; CompType: Resistor; Value: 9.1k; Res_ohm: 9100; Value_Code: 9k10; Tolerance_%: 5; Power_W: 0.1; Value2: 0.1W; VDC_V: 50; TempCo: 100 ppm/C; SizeArea_mm2: 1.28; SizeX_mm: 1.6; SizeY_mm: 0.8; SizeZ_mm: 1; EIA_Code: E24; U/M: EA; AEC Category: Q200
signal-integrity model Resistor
simulation model Resistor
footprint 0603
footprint 0603M
footprint 0603L
footprint 0603_HV
footprint 0603S
pins: 1, 2

## RC0603JR-0710KL
designator R?  ValueDisplayed: 10k  (hidden comment: RC0603JR-0710KL)
RES, 10 k, 5%, 0.1 W, 0603; Manufacturer: Yageo America; CompType: Resistor; Value: 10k; Res_ohm: 10000; Value_Code: 10k0; Tolerance_%: 5; Power_W: 0.1; Value2: 0.1W; VDC_V: 50; TempCo: 100 ppm/C; SizeArea_mm2: 1.28; SizeX_mm: 1.6; SizeY_mm: 0.8; SizeZ_mm: 1; EIA_Code: E24; U/M: EA; AEC Category: Q200; Green_Lifecycle: Active; Green_REACh: Passed
signal-integrity model Resistor
simulation model Resistor
footprint 0603
footprint 0603M
footprint 0603L
footprint 0603_HV
footprint 0603S
pins: 1, 2

## RC0603JR-0711KL
designator R?  ValueDisplayed: 11k  (hidden comment: RC0603JR-0711KL)
RES, 11 k, 5%, 0.1 W, 0603; Manufacturer: Yageo America; CompType: Resistor; Value: 11k; Res_ohm: 11000; Value_Code: 11k0; Tolerance_%: 5; Power_W: 0.1; Value2: 0.1W; VDC_V: 50; TempCo: 100 ppm/C; SizeArea_mm2: 1.28; SizeX_mm: 1.6; SizeY_mm: 0.8; SizeZ_mm: 1; EIA_Code: E24; U/M: EA; AEC Category: Q200
signal-integrity model Resistor
simulation model Resistor
footprint 0603
footprint 0603M
footprint 0603L
footprint 0603_HV
footprint 0603S
pins: 1, 2

## RC0603JR-0712KL
designator R?  ValueDisplayed: 12k  (hidden comment: RC0603JR-0712KL)
RES, 12 k, 5%, 0.1 W, 0603; Manufacturer: Yageo America; CompType: Resistor; Value: 12k; Res_ohm: 12000; Value_Code: 12k0; Tolerance_%: 5; Power_W: 0.1; Value2: 0.1W; VDC_V: 50; TempCo: 100 ppm/C; SizeArea_mm2: 1.28; SizeX_mm: 1.6; SizeY_mm: 0.8; SizeZ_mm: 1; EIA_Code: E24; U/M: EA; AEC Category: Q200
signal-integrity model Resistor
simulation model Resistor
footprint 0603
footprint 0603M
footprint 0603L
footprint 0603_HV
footprint 0603S
pins: 1, 2

## RC0603JR-0713KL
designator R?  ValueDisplayed: 13k  (hidden comment: RC0603JR-0713KL)
RES, 13 k, 5%, 0.1 W, 0603; Manufacturer: Yageo America; CompType: Resistor; Value: 13k; Res_ohm: 13000; Value_Code: 13k0; Tolerance_%: 5; Power_W: 0.1; Value2: 0.1W; VDC_V: 50; TempCo: 100 ppm/C; SizeArea_mm2: 1.28; SizeX_mm: 1.6; SizeY_mm: 0.8; SizeZ_mm: 1; EIA_Code: E24; U/M: EA; AEC Category: Q200
signal-integrity model Resistor
simulation model Resistor
footprint 0603
footprint 0603M
footprint 0603L
footprint 0603_HV
footprint 0603S
pins: 1, 2

## RC0603JR-0715KL
designator R?  ValueDisplayed: 15k  (hidden comment: RC0603JR-0715KL)
RES, 15 k, 5%, 0.1 W, 0603; Manufacturer: Yageo America; CompType: Resistor; Value: 15k; Res_ohm: 15000; Value_Code: 15k0; Tolerance_%: 5; Power_W: 0.1; Value2: 0.1W; VDC_V: 50; TempCo: 100 ppm/C; SizeArea_mm2: 1.28; SizeX_mm: 1.6; SizeY_mm: 0.8; SizeZ_mm: 1; EIA_Code: E24; U/M: EA; AEC Category: Q200
signal-integrity model Resistor
simulation model Resistor
footprint 0603
footprint 0603M
footprint 0603L
footprint 0603_HV
footprint 0603S
pins: 1, 2

## RC0603JR-0716KL
designator R?  ValueDisplayed: 16k  (hidden comment: RC0603JR-0716KL)
RES, 16 k, 5%, 0.1 W, 0603; Manufacturer: Yageo America; CompType: Resistor; Value: 16k; Res_ohm: 16000; Value_Code: 16k0; Tolerance_%: 5; Power_W: 0.1; Value2: 0.1W; VDC_V: 50; TempCo: 100 ppm/C; SizeArea_mm2: 1.28; SizeX_mm: 1.6; SizeY_mm: 0.8; SizeZ_mm: 1; EIA_Code: E24; U/M: EA; AEC Category: Q200
signal-integrity model Resistor
simulation model Resistor
footprint 0603
footprint 0603M
footprint 0603L
footprint 0603_HV
footprint 0603S
pins: 1, 2

## RC0603JR-0718KL
designator R?  ValueDisplayed: 18k  (hidden comment: RC0603JR-0718KL)
RES, 18 k, 5%, 0.1 W, 0603; Manufacturer: Yageo America; CompType: Resistor; Value: 18k; Res_ohm: 18000; Value_Code: 18k0; Tolerance_%: 5; Power_W: 0.1; Value2: 0.1W; VDC_V: 50; TempCo: 100 ppm/C; SizeArea_mm2: 1.28; SizeX_mm: 1.6; SizeY_mm: 0.8; SizeZ_mm: 1; EIA_Code: E24; U/M: EA; AEC Category: Q200; Green_Lifecycle: Active; Green_REACh: Passed
signal-integrity model Resistor
simulation model Resistor
footprint 0603
footprint 0603M
footprint 0603L
footprint 0603_HV
footprint 0603S
pins: 1, 2

## RC0603JR-0720KL
designator R?  ValueDisplayed: 20k  (hidden comment: RC0603JR-0720KL)
RES, 20 k, 5%, 0.1 W, 0603; Manufacturer: Yageo America; CompType: Resistor; Value: 20k; Res_ohm: 20000; Value_Code: 20k0; Tolerance_%: 5; Power_W: 0.1; Value2: 0.1W; VDC_V: 50; TempCo: 100 ppm/C; SizeArea_mm2: 1.28; SizeX_mm: 1.6; SizeY_mm: 0.8; SizeZ_mm: 1; EIA_Code: E24; U/M: EA; AEC Category: Q200
signal-integrity model Resistor
simulation model Resistor
footprint 0603
footprint 0603M
footprint 0603L
footprint 0603_HV
footprint 0603S
pins: 1, 2

## RC0603JR-0722KL
designator R?  ValueDisplayed: 22k  (hidden comment: RC0603JR-0722KL)
RES, 22 k, 5%, 0.1 W, 0603; Manufacturer: Yageo America; CompType: Resistor; Value: 22k; Res_ohm: 22000; Value_Code: 22k0; Tolerance_%: 5; Power_W: 0.1; Value2: 0.1W; VDC_V: 50; TempCo: 100 ppm/C; SizeArea_mm2: 1.28; SizeX_mm: 1.6; SizeY_mm: 0.8; SizeZ_mm: 1; EIA_Code: E24; U/M: EA; AEC Category: Q200
signal-integrity model Resistor
simulation model Resistor
footprint 0603
footprint 0603M
footprint 0603L
footprint 0603_HV
footprint 0603S
pins: 1, 2

## RC0603JR-0724KL
designator R?  ValueDisplayed: 24k  (hidden comment: RC0603JR-0724KL)
RES, 24 k, 5%, 0.1 W, 0603; Manufacturer: Yageo America; CompType: Resistor; Value: 24k; Res_ohm: 24000; Value_Code: 24k0; Tolerance_%: 5; Power_W: 0.1; Value2: 0.1W; VDC_V: 50; TempCo: 100 ppm/C; SizeArea_mm2: 1.28; SizeX_mm: 1.6; SizeY_mm: 0.8; SizeZ_mm: 1; EIA_Code: E24; U/M: EA; AEC Category: Q200
signal-integrity model Resistor
simulation model Resistor
footprint 0603
footprint 0603M
footprint 0603L
footprint 0603_HV
footprint 0603S
pins: 1, 2

## RC0603JR-0727KL
designator R?  ValueDisplayed: 27k  (hidden comment: RC0603JR-0727KL)
RES, 27 k, 5%, 0.1 W, 0603; Manufacturer: Yageo America; CompType: Resistor; Value: 27k; Res_ohm: 27000; Value_Code: 27k0; Tolerance_%: 5; Power_W: 0.1; Value2: 0.1W; VDC_V: 50; TempCo: 100 ppm/C; SizeArea_mm2: 1.28; SizeX_mm: 1.6; SizeY_mm: 0.8; SizeZ_mm: 1; EIA_Code: E24; U/M: EA; AEC Category: Q200
signal-integrity model Resistor
simulation model Resistor
footprint 0603
footprint 0603M
footprint 0603L
footprint 0603_HV
footprint 0603S
pins: 1, 2

## RC0603JR-0730KL
designator R?  ValueDisplayed: 30k  (hidden comment: RC0603JR-0730KL)
RES, 30 k, 5%, 0.1 W, 0603; Manufacturer: Yageo America; CompType: Resistor; Value: 30k; Res_ohm: 30000; Value_Code: 30k0; Tolerance_%: 5; Power_W: 0.1; Value2: 0.1W; VDC_V: 50; TempCo: 100 ppm/C; SizeArea_mm2: 1.28; SizeX_mm: 1.6; SizeY_mm: 0.8; SizeZ_mm: 1; EIA_Code: E24; U/M: EA; AEC Category: Q200
signal-integrity model Resistor
simulation model Resistor
footprint 0603
footprint 0603M
footprint 0603L
footprint 0603_HV
footprint 0603S
pins: 1, 2

## RC0603JR-0733KL
designator R?  ValueDisplayed: 33k  (hidden comment: RC0603JR-0733KL)
RES, 33 k, 5%, 0.1 W, 0603; Manufacturer: Yageo America; CompType: Resistor; Value: 33k; Res_ohm: 33000; Value_Code: 33k0; Tolerance_%: 5; Power_W: 0.1; Value2: 0.1W; VDC_V: 50; TempCo: 100 ppm/C; SizeArea_mm2: 1.28; SizeX_mm: 1.6; SizeY_mm: 0.8; SizeZ_mm: 1; EIA_Code: E24; U/M: EA; AEC Category: Q200
signal-integrity model Resistor
simulation model Resistor
footprint 0603
footprint 0603M
footprint 0603L
footprint 0603_HV
footprint 0603S
pins: 1, 2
